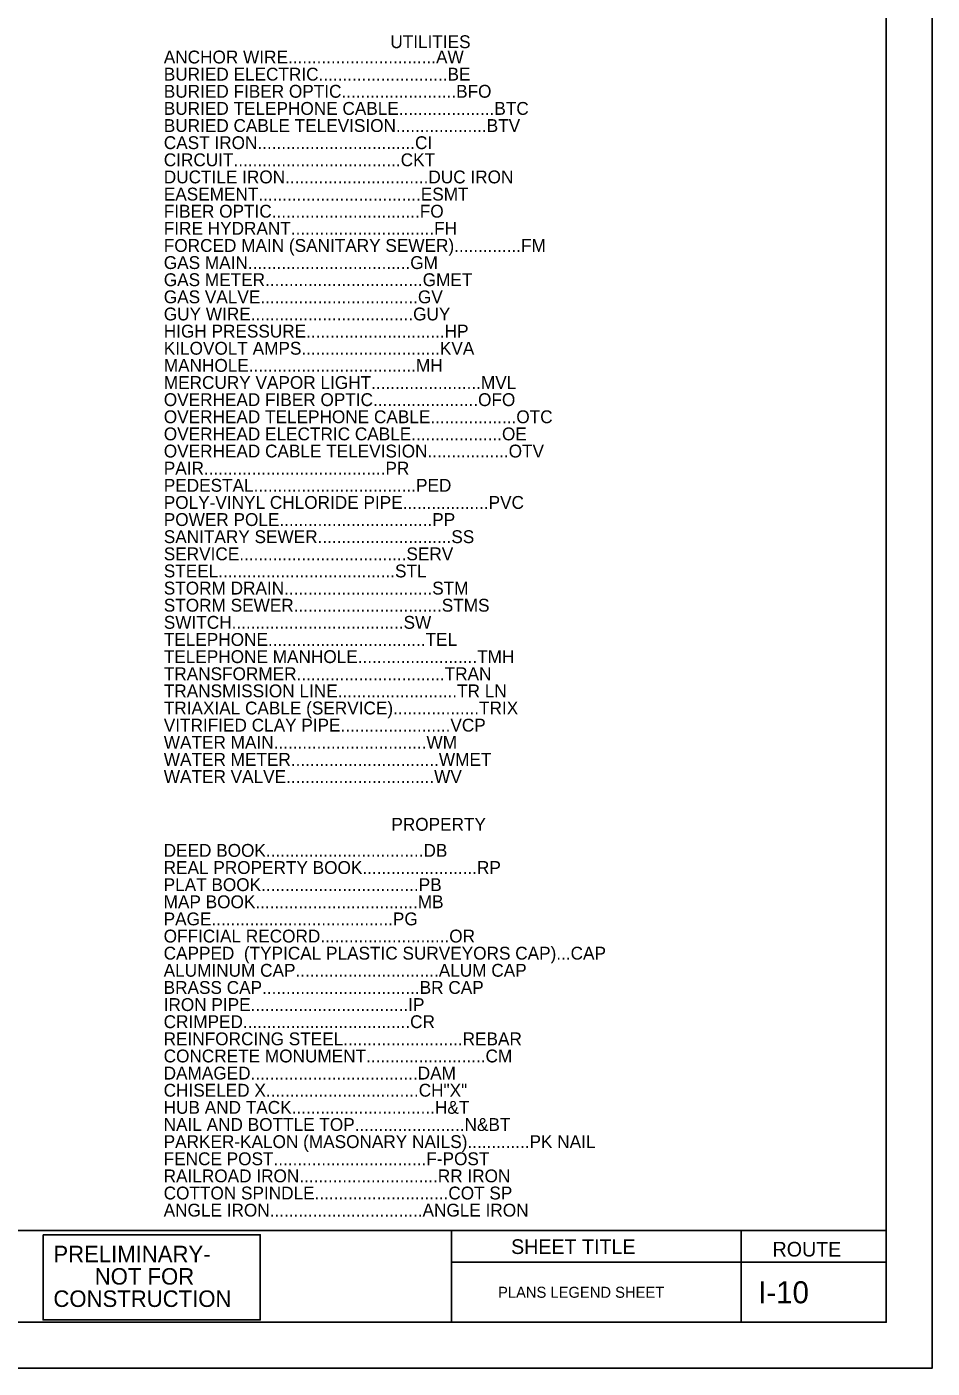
# Model space of a CAD drawing. Extents: x 0 to 1700, y 31 to 1131.
# Drawn here: x 1207 to 1700, y 31 to 761 of the extents above; entities that cross this region are included whole.
import ezdxf

# ---------------------------------------------------------------- set-up
doc = ezdxf.new("R2010")
doc.units = 0
for name, color, linetype in [('1', 7, 'Continuous'), ('ANNO-SHT', 7, 'Continuous'), ('ANNO-TXT', 7, 'Continuous'), ('LEGEND', 7, 'Continuous'), ('Level 1', 7, 'Continuous'), ('Level 6', 7, 'Continuous'), ('Level 62', 7, 'Continuous'), ('SHT-BDR', 7, 'Continuous'), ('SHT-BNDRY', 7, 'Continuous')]:
    doc.layers.add(name, color=color, linetype=linetype)

msp = doc.modelspace()

# ---------------------------------------------------------------- linework, layer by layer
at = {"layer": '1'}
msp.add_lwpolyline([(1215.92, 103.31), (1334.13, 103.31), (1334.13, 56.99), (1215.92, 56.99)], close=True, dxfattribs=at)
at = {"layer": 'ANNO-TXT'}
for p, q in [((1438.3, 88.36), (1595.94, 88.36)), ((1595.94, 88.36), (1675, 88.36))]:
    msp.add_line(p, q, dxfattribs=at)
at = {"layer": 'Level 6'}
msp.add_line((1675, 105.71), (1438.3, 105.71), dxfattribs=at)
at = {"layer": 'Level 62'}
msp.add_lwpolyline([(0, 30.66), (1700, 30.66), (1700, 1130.66), (0, 1130.66)], close=True, dxfattribs=at)
at = {"layer": 'SHT-BDR'}
msp.add_lwpolyline([(62.5, 105.71), (1675, 105.71)], dxfattribs=at)
at = {"layer": 'SHT-BNDRY'}
for p, q in [((1438.3, 55.66), (1438.3, 105.71)), ((1595.94, 55.66), (1595.94, 105.71))]:
    msp.add_line(p, q, dxfattribs=at)
msp.add_lwpolyline([(62.5, 55.66), (1675, 55.66), (1675, 1105.66), (62.5, 1105.66)], close=True, dxfattribs=at)

# ---------------------------------------------------------------- texts
at = {"layer": '1'}
for s, p in [('PRELIMINARY-', (1221.51, 88.37)), ('NOT FOR', (1244.03, 76.2)), ('CONSTRUCTION', (1221.53, 64.02))]:
    msp.add_text(s, height=9, dxfattribs=at).set_placement(p)
at = {"layer": 'ANNO-SHT'}
for s, height, p in [('PLANS LEGEND SHEET', 6, (1463.62, 69.01)), ('  I-10  ', 12, (1596.34, 66.01))]:
    msp.add_text(s, height=height, dxfattribs=at).set_placement(p)
at = {"layer": 'ANNO-TXT'}
for s, p in [('SHEET TITLE', (1470.73, 92.87)), ('ROUTE', (1613.09, 91.47))]:
    msp.add_text(s, height=8, dxfattribs=at).set_placement(p)
at = {"layer": 'LEGEND'}
for s, p in [('UTILITIES', (1404.99, 749.83)), ('PROPERTY', (1405.55, 323.46))]:
    msp.add_text(s, height=7, dxfattribs=at).set_placement(p)
at = {"layer": 'Level 1'}
for s, p in [('ANCHOR WIRE...............................AW', (1281.64, 741.49)), ('BURIED ELECTRIC...........................BE', (1281.64, 732.16)), ('BURIED FIBER OPTIC........................BFO', (1281.64, 722.82)), ('BURIED TELEPHONE CABLE....................BTC', (1281.64, 713.49)), ('BURIED CABLE TELEVISION...................BTV', (1281.64, 704.16)), ('CAST IRON.................................CI', (1281.64, 694.82)), ('CIRCUIT...................................CKT', (1281.64, 685.49)), ('DUCTILE IRON..............................DUC IRON', (1281.64, 676.16)), ('EASEMENT..................................ESMT', (1281.64, 666.82)), ('FIBER OPTIC...............................FO', (1281.64, 657.49)), ('FIRE HYDRANT..............................FH', (1281.64, 648.16)), ('FORCED MAIN (SANITARY SEWER)..............FM', (1281.64, 638.82)), ('GAS MAIN..................................GM', (1281.64, 629.49)), ('GAS METER.................................GMET', (1281.64, 620.16)), ('GAS VALVE.................................GV', (1281.64, 610.82)), ('GUY WIRE..................................GUY', (1281.64, 601.49)), ('HIGH PRESSURE.............................HP', (1281.64, 592.16)), ('KILOVOLT AMPS.............................KVA', (1281.64, 582.82)), ('MANHOLE...................................MH', (1281.64, 573.49)), ('MERCURY VAPOR LIGHT.......................MVL', (1281.64, 564.16)), ('OVERHEAD FIBER OPTIC......................OFO', (1281.64, 554.82)), ('OVERHEAD TELEPHONE CABLE..................OTC', (1281.64, 545.49)), ('OVERHEAD ELECTRIC CABLE...................OE', (1281.64, 536.16)), ('OVERHEAD CABLE TELEVISION.................OTV', (1281.64, 526.82)), ('PAIR......................................PR', (1281.64, 517.49)), ('PEDESTAL..................................PED', (1281.64, 508.16)), ('POLY-VINYL CHLORIDE PIPE..................PVC', (1281.64, 498.82)), ('POWER POLE................................PP', (1281.64, 489.49)), ('SANITARY SEWER............................SS', (1281.64, 480.16)), ('SERVICE...................................SERV', (1281.64, 470.82)), ('STEEL.....................................STL', (1281.64, 461.49)), ('STORM DRAIN...............................STM', (1281.64, 452.16)), ('STORM SEWER...............................STMS', (1281.64, 442.82)), ('SWITCH....................................SW', (1281.64, 433.49)), ('TELEPHONE.................................TEL', (1281.64, 424.16)), ('TELEPHONE MANHOLE.........................TMH', (1281.64, 414.82)), ('TRANSFORMER...............................TRAN', (1281.64, 405.49)), ('TRANSMISSION LINE.........................TR LN', (1281.64, 396.16)), ('TRIAXIAL CABLE (SERVICE)..................TRIX', (1281.64, 386.82)), ('VITRIFIED CLAY PIPE.......................VCP', (1281.64, 377.49)), ('WATER MAIN................................WM', (1281.64, 368.16)), ('WATER METER...............................WMET', (1281.64, 358.82)), ('WATER VALVE...............................WV', (1281.64, 349.49)), ('DEED BOOK.................................DB', (1281.56, 309.25)), ('REAL PROPERTY BOOK........................RP', (1281.56, 299.92)), ('PLAT BOOK.................................PB', (1281.56, 290.58)), ('MAP BOOK..................................MB', (1281.56, 281.25)), ('PAGE......................................PG', (1281.56, 271.92)), ('OFFICIAL RECORD...........................OR', (1281.56, 262.58)), ('CAPPED  (TYPICAL PLASTIC SURVEYORS CAP)...CAP', (1281.56, 253.25)), ('ALUMINUM CAP..............................ALUM CAP', (1281.56, 243.92)), ('BRASS CAP.................................BR CAP', (1281.56, 234.58)), ('IRON PIPE.................................IP', (1281.56, 225.25)), ('CRIMPED...................................CR', (1281.56, 215.92)), ('REINFORCING STEEL.........................REBAR', (1281.56, 206.58)), ('CONCRETE MONUMENT.........................CM', (1281.56, 197.25)), ('DAMAGED...................................DAM', (1281.56, 187.92)), ('CHISELED X................................CH"X"', (1281.56, 178.58)), ('HUB AND TACK..............................H&T', (1281.56, 169.25)), ('NAIL AND BOTTLE TOP.......................N&BT', (1281.56, 159.92)), ('PARKER-KALON (MASONARY NAILS).............PK NAIL', (1281.56, 150.58)), ('FENCE POST................................F-POST', (1281.56, 141.25)), ('RAILROAD IRON.............................RR IRON', (1281.56, 131.92)), ('COTTON SPINDLE............................COT SP', (1281.56, 122.58)), ('ANGLE IRON................................ANGLE IRON', (1281.56, 113.25))]:
    msp.add_text(s, height=7, dxfattribs=at).set_placement(p)

doc.saveas('drawing.dxf')
